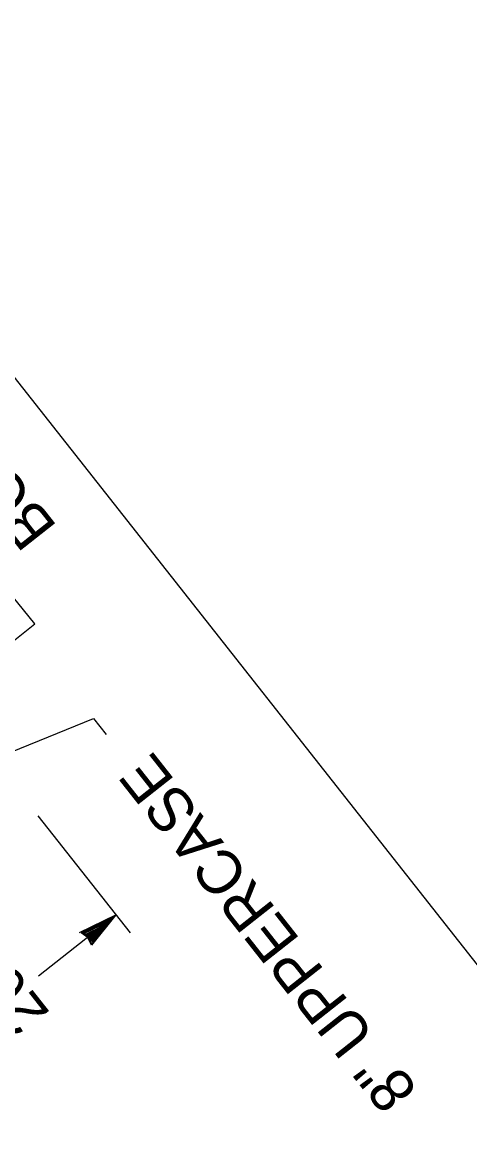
# Model space of a CAD drawing. Extents: x 672239 to 673995, y 1673540 to 1675195.
# Drawn here: x 672510.8 to 672553.6, y 1674940 to 1675045.8 of the extents above; entities that cross this region are included whole.
import ezdxf

# ---------------------------------------------------------------- set-up
doc = ezdxf.new("R2010")
doc.units = 0
doc.layers.add('C-ALGN-SYMB', color=7, linetype='Continuous')
doc.layers.add('C-HELI-SIDE', color=7, linetype='Continuous')

msp = doc.modelspace()

# ---------------------------------------------------------------- linework, layer by layer
at = {"layer": 'C-ALGN-SYMB'}
for p, q in [((672512.25, 1674969.98), (672521.08, 1674958.78)), ((672512.33, 1674954.69), (672519.72, 1674960.51)), ((672516.25, 1674958.81), (672519.72, 1674960.51)), ((672516.45, 1674958.86), (672519.29, 1674960.16)), ((672516.61, 1674958.83), (672519.46, 1674960.25)), ((672516.73, 1674958.75), (672518.93, 1674959.9)), ((672518.93, 1674959.9), (672517.37, 1674958.19)), ((672519.72, 1674960.51), (672517.39, 1674957.61)), ((672519.5, 1674960.28), (672517.41, 1674957.75)), ((672519.15, 1674960), (672517.41, 1674957.92)), ((672519.25, 1674960.22), (672518.45, 1674959.79)), ((672518.45, 1674959.79), (672519.15, 1674960)), ((672519.46, 1674960.25), (672519.25, 1674960.22)), ((672519.29, 1674960.16), (672519.5, 1674960.28)), ((672516.76, 1674958.68), (672516.45, 1674958.86)), ((672516.73, 1674958.75), (672518.86, 1674959.78)), ((672516.91, 1674958.69), (672518.42, 1674959.44)), ((672517.07, 1674958.65), (672518.03, 1674959.17)), ((672517.18, 1674958.61), (672517.7, 1674958.88)), ((672517.37, 1674958.32), (672517.87, 1674959.08)), ((672518.86, 1674959.78), (672517.41, 1674958.05)), ((672518.42, 1674959.44), (672517.43, 1674958.33)), ((672517.7, 1674958.88), (672517.43, 1674958.54)), ((672518.03, 1674959.17), (672517.46, 1674958.46)), ((672517.87, 1674959.08), (672518.13, 1674959.18)), ((672518.49, 1674959.53), (672518.05, 1674959.32)), ((672518.13, 1674959.18), (672518.49, 1674959.53)), ((672517.07, 1674958.32), (672516.4, 1674958.79)), ((672516.4, 1674958.79), (672516.62, 1674958.73)), ((672516.62, 1674958.73), (672516.61, 1674958.83)), ((672517.28, 1674958.18), (672516.73, 1674958.75)), ((672517.41, 1674958.05), (672516.73, 1674958.75)), ((672517, 1674958.37), (672516.76, 1674958.68)), ((672517.37, 1674958.19), (672516.91, 1674958.69)), ((672517.35, 1674958.6), (672516.99, 1674958.59)), ((672516.99, 1674958.59), (672517.37, 1674958.32)), ((672517.39, 1674957.61), (672517, 1674958.37)), ((672517.43, 1674958.33), (672517.07, 1674958.65)), ((672517.41, 1674957.75), (672517.07, 1674958.32)), ((672517.46, 1674958.46), (672517.18, 1674958.61)), ((672517.41, 1674957.92), (672517.28, 1674958.18)), ((672517.43, 1674958.54), (672517.35, 1674958.6))]:
    msp.add_line(p, q, dxfattribs=at)
for points in [[(672502.85, 1674981.07), (672511.96, 1674988.33), (672508.83, 1674992.19)], [(672494.85, 1674970.04), (672517.57, 1674979.29), (672518.79, 1674977.74)]]:
    msp.add_lwpolyline(points, dxfattribs=at)
at = {"layer": 'C-HELI-SIDE'}
msp.add_lwpolyline([(672667.2, 1675019.19), (672536.15, 1675185.41), (672435.66, 1675106.18), (672566.7, 1674939.96)], close=True, dxfattribs=at)

# ---------------------------------------------------------------- texts
at = {"layer": 'C-ALGN-SYMB'}
for s, p in [('BORDER STRIP', (672514.19, 1674997.58)), ('8" UPPERCASE', (672548.71, 1674943.79)), ('26"', (672513.5, 1674951.11))]:
    msp.add_text(s, height=4.2, rotation=128.2505, dxfattribs=at).set_placement(p)

doc.saveas('drawing.dxf')
